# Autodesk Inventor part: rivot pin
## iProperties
Author: Rich
Shininess: 25.0
PropertySet Name: _Private Model Information
Created: 2001-04
Part Number: rivot pin
Document SubType Name: Modeling
Designer: Rich
Control State: 0
Master: False
Checked Out: False
PropertySet Name: Design Tracking Control
Density: 0.0
Volumn: 0.0
Area: 0.0
PropertySet Name: Model Information
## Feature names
1. Revolution1
